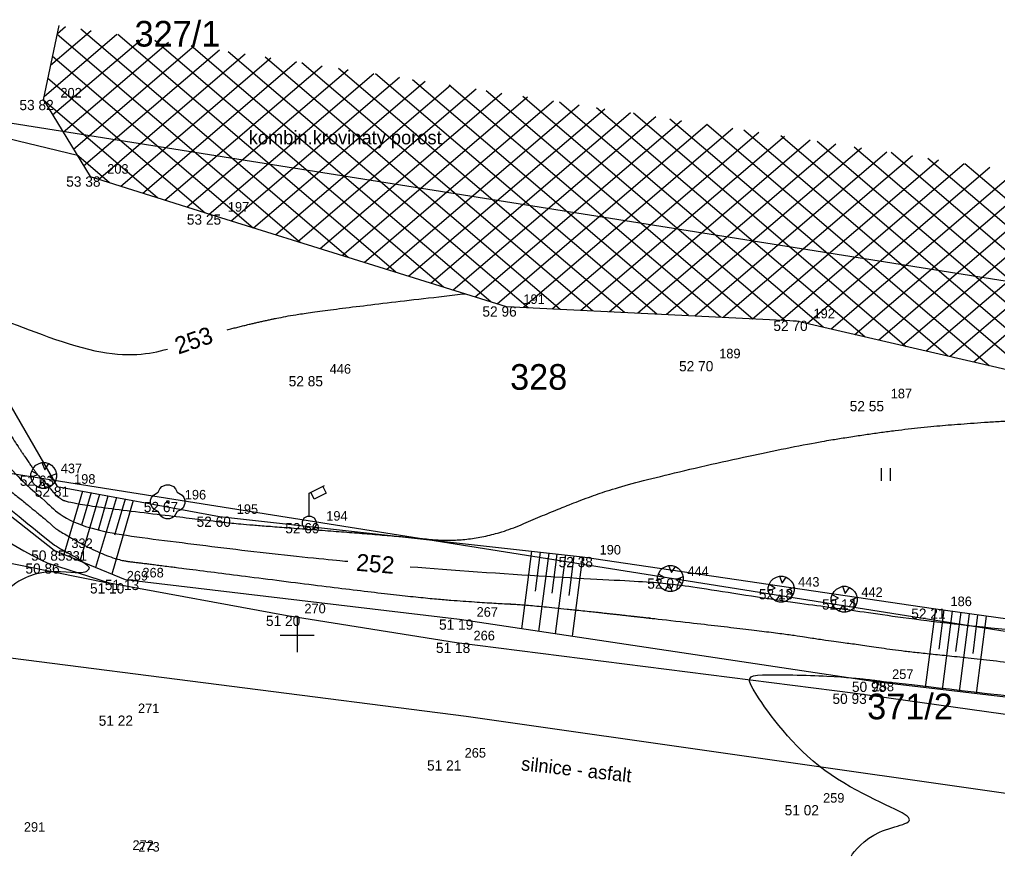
# Model space of a CAD drawing. Extents: x -704057 to -703795, y -1008732 to -1008584.
# Drawn here: x -703983.13 to -703954.51, y -1008656.35 to -1008631.99 of the extents above; entities that cross this region are included whole.
import ezdxf

# ---------------------------------------------------------------- set-up
doc = ezdxf.new("R2010")
doc.units = 0
for name, color, linetype in [('Z_body', 7, 'Continuous'), ('Z_body_cisla', 7, 'Continuous'), ('Z_body_vysky', 7, 'Continuous'), ('Z_hekt_sit', 7, 'Continuous'), ('Z_katastr_cisla_pozemkove', 7, 'Continuous'), ('Z_katastr_hranice', 7, 'Continuous'), ('Z_katastr_hranice_KU', 7, 'Continuous'), ('Z_komunikace_zpevn_pl', 7, 'Continuous'), ('Z_popis', 7, 'Continuous'), ('Z_site_znaky_VO', 7, 'Continuous'), ('Z_teren_hrany_paty', 7, 'Continuous'), ('Z_vrstevnice_popis', 7, 'Continuous'), ('Z_vrstevnice_vedlejsi', 7, 'Continuous'), ('Z_zelen_jednotliva', 7, 'Continuous'), ('Z_zelen_souvisla', 7, 'Continuous')]:
    doc.layers.add(name, color=color, linetype=linetype)

# ---------------------------------------------------------------- blocks, each defined once
blk = doc.blocks.new('POINT_DISPLAY')
blk.add_line((0, 0), (0, 0))
blk = doc.blocks.new('Z24')
for p, q in [((-0.28, 0.28), (-0.23, 0.38)), ((-0.23, 0.38), (-0.17, 0.45)), ((-0.17, 0.45), (-0.05, 0.5)), ((-0.05, 0.5), (0.05, 0.5)), ((0.05, 0.5), (0.17, 0.45)), ((0.17, 0.45), (0.23, 0.38)), ((0.23, 0.38), (0.28, 0.28)), ((-0.5, 0.05), (-0.47, 0.13)), ((-0.5, -0.05), (-0.5, 0.05)), ((-0.47, 0.13), (-0.42, 0.2)), ((-0.42, 0.2), (-0.28, 0.28)), ((-0.03, -0.03), (-0.03, 0.03)), ((-0.03, 0.03), (0.03, 0.03)), ((0.03, 0.03), (0.03, -0.03)), ((0.28, 0.28), (0.42, 0.2)), ((0.42, 0.2), (0.47, 0.13)), ((0.47, 0.13), (0.5, 0.05)), ((0.5, 0.05), (0.5, -0.05)), ((-0.45, -0.17), (-0.5, -0.05)), ((-0.38, -0.23), (-0.45, -0.17)), ((-0.28, -0.28), (-0.38, -0.23)), ((-0.2, -0.42), (-0.28, -0.28)), ((0.03, -0.03), (-0.03, -0.03)), ((0.28, -0.28), (0.2, -0.42)), ((0.38, -0.23), (0.28, -0.28)), ((0.45, -0.17), (0.38, -0.23)), ((0.5, -0.05), (0.45, -0.17)), ((-0.13, -0.47), (-0.2, -0.42)), ((-0.05, -0.5), (-0.13, -0.47)), ((0.05, -0.5), (-0.05, -0.5)), ((0.13, -0.47), (0.05, -0.5)), ((0.2, -0.42), (0.13, -0.47))]:
    blk.add_line(p, q)
blk = doc.blocks.new('Z23')
for p, q in [((-0.3, 0.23), (-0.23, 0.3)), ((-0.23, 0.3), (-0.13, 0.35)), ((-0.13, 0.35), (-0.05, 0.38)), ((-0.05, 0.38), (0.05, 0.38)), ((-0.05, 0.38), (0.03, 0.17)), ((0.03, 0.17), (0.15, 0.35)), ((0.05, 0.38), (0.15, 0.35)), ((0.15, 0.35), (0.23, 0.3)), ((0.23, 0.3), (0.3, 0.23)), ((-0.38, 0.05), (-0.35, 0.13)), ((-0.38, -0.05), (-0.38, 0.05)), ((-0.38, -0.05), (-0.17, 0.03)), ((-0.35, 0.13), (-0.3, 0.23)), ((-0.17, 0.03), (-0.35, 0.13)), ((0.38, 0.05), (0.17, -0.03)), ((0.3, 0.23), (0.35, 0.15)), ((0.35, 0.15), (0.38, 0.05)), ((0.38, 0.05), (0.38, -0.05)), ((-0.35, -0.13), (-0.38, -0.05)), ((-0.3, -0.23), (-0.35, -0.13)), ((-0.23, -0.3), (-0.3, -0.23)), ((-0.15, -0.35), (-0.03, -0.17)), ((-0.03, -0.17), (0.05, -0.38)), ((0.17, -0.03), (0.35, -0.15)), ((0.3, -0.23), (0.23, -0.3)), ((0.35, -0.15), (0.3, -0.23)), ((0.38, -0.05), (0.35, -0.15)), ((-0.15, -0.35), (-0.23, -0.3)), ((-0.05, -0.38), (-0.15, -0.35)), ((0.05, -0.38), (-0.05, -0.38)), ((0.15, -0.35), (0.05, -0.38)), ((0.23, -0.3), (0.15, -0.35))]:
    blk.add_line(p, q)
blk = doc.blocks.new('Z13')
for p, q in [((0, 0.88), (0.45, 1.1)), ((0, 0.2), (0, 0.88)), ((0.15, 0.7), (0.05, 0.9)), ((0.5, 0.88), (0.15, 0.7)), ((0.4, 1.07), (0.5, 0.88)), ((-0.2, 0.05), (-0.15, 0.15)), ((-0.2, -0.05), (-0.2, 0.05)), ((-0.15, 0.15), (-0.05, 0.2)), ((-0.05, 0.2), (0.05, 0.2)), ((0.05, 0.2), (0.15, 0.15)), ((0.15, 0.15), (0.2, 0.05)), ((0.2, 0.05), (0.2, -0.05)), ((-0.15, -0.15), (-0.2, -0.05)), ((-0.05, -0.2), (-0.15, -0.15)), ((0.05, -0.2), (-0.05, -0.2)), ((0.15, -0.15), (0.05, -0.2)), ((0.2, -0.05), (0.15, -0.15))]:
    blk.add_line(p, q)
blk = doc.blocks.new('Z306')
for p, q in [((-0.13, 0.17), (-0.13, -0.2)), ((0.13, 0.17), (0.13, -0.2))]:
    blk.add_line(p, q)

msp = doc.modelspace()

# ---------------------------------------------------------------- linework, layer by layer
at = {"layer": 'Z_hekt_sit'}
for p, q in [((-703975, -1008649.5), (-703975, -1008650.5)), ((-703975.5, -1008650), (-703974.5, -1008650))]:
    msp.add_line(p, q, dxfattribs=at)
at = {"layer": 'Z_katastr_hranice'}
for p, q in [((-703948.06, -1008640.63), (-703989.44, -1008634.06)), ((-703993.4, -1008643.68), (-703944.4, -1008651.45))]:
    msp.add_line(p, q, dxfattribs=at)
at = {"layer": 'Z_katastr_hranice_KU'}
for p, q in [((-703989.65, -1008649.86), (-703970.06, -1008652.37)), ((-703970.06, -1008652.37), (-703947.15, -1008655.63))]:
    msp.add_line(p, q, dxfattribs=at)
at = {"layer": 'Z_komunikace_zpevn_pl'}
for p, q in [((-703988.96, -1008646.77), (-703980.49, -1008648.48)), ((-703980.49, -1008648.48), (-703982.28, -1008647.9)), ((-703975.29, -1008649.43), (-703980.49, -1008648.48)), ((-703970.34, -1008650.22), (-703975.29, -1008649.43)), ((-703958.66, -1008651.71), (-703970.34, -1008650.22)), ((-703949.88, -1008652.93), (-703958.66, -1008651.71))]:
    msp.add_line(p, q, dxfattribs=at)
msp.add_arc((-703977.91, -1008638.41), 10.448, 198.1269, 245.2768, dxfattribs=at)
at = {"layer": 'Z_teren_hrany_paty'}
for p, q in [((-703984.91, -1008640.66), (-703982.03, -1008645.65)), ((-703982.11, -1008647.52), (-703985.68, -1008644.72)), ((-703982.03, -1008645.65), (-703977.27, -1008646.53)), ((-703981.28, -1008645.79), (-703981.83, -1008647.64)), ((-703980.79, -1008645.88), (-703981.36, -1008647.83)), ((-703981.03, -1008645.83), (-703981.31, -1008646.78)), ((-703980.29, -1008645.97), (-703980.9, -1008648.02)), ((-703980.54, -1008645.93), (-703980.83, -1008646.93)), ((-703980.04, -1008646.02), (-703980.35, -1008647.07)), ((-703979.8, -1008646.06), (-703980.43, -1008648.21)), ((-703977.27, -1008646.53), (-703966.65, -1008647.71)), ((-703980.03, -1008648.38), (-703982.11, -1008647.52)), ((-703968.14, -1008647.54), (-703968.44, -1008649.81)), ((-703967.89, -1008647.57), (-703968.04, -1008648.71)), ((-703967.64, -1008647.6), (-703967.94, -1008649.89)), ((-703967.4, -1008647.63), (-703967.55, -1008648.77)), ((-703967.15, -1008647.65), (-703967.45, -1008649.96)), ((-703966.9, -1008647.68), (-703967.05, -1008648.84)), ((-703966.65, -1008647.71), (-703966.95, -1008650.03)), ((-703966.65, -1008647.71), (-703956.38, -1008649.22)), ((-703970.25, -1008649.54), (-703980.03, -1008648.38)), ((-703956.32, -1008649.23), (-703956.62, -1008651.53)), ((-703956.38, -1008649.22), (-703947.47, -1008650.47)), ((-703956.08, -1008649.26), (-703956.22, -1008650.41)), ((-703955.83, -1008649.3), (-703956.12, -1008651.59)), ((-703955.58, -1008649.33), (-703955.73, -1008650.48)), ((-703955.33, -1008649.37), (-703955.63, -1008651.65)), ((-703955.09, -1008649.4), (-703955.23, -1008650.54)), ((-703954.84, -1008649.44), (-703955.13, -1008651.71)), ((-703958.09, -1008651.36), (-703970.25, -1008649.54)), ((-703949.1, -1008652.42), (-703958.09, -1008651.36))]:
    msp.add_line(p, q, dxfattribs=at)
at = {"layer": 'Z_vrstevnice_popis'}
for points, degree in [([(-703989.544, -1008635.313), (-703988.902, -1008636.056), (-703987.798, -1008637.865), (-703987.151, -1008639.438), (-703986.053, -1008641.144), (-703985.706, -1008641.697), (-703984.977, -1008642.908), (-703983.536, -1008645.121), (-703982.31, -1008646.105), (-703982.063, -1008646.423), (-703981.066, -1008646.966), (-703978.397, -1008647.285), (-703975.56, -1008647.648), (-703973.643, -1008647.827), (-703973.517, -1008647.838)], 3), ([(-703987.108, -1008635.508), (-703986.754, -1008636.087), (-703984.996, -1008640.365), (-703984.718, -1008640.456), (-703984.363, -1008640.44), (-703980.63, -1008641.987), (-703979.311, -1008641.778), (-703978.799, -1008641.628)], 3), ([(-703977.053, -1008641.068), (-703976.067, -1008640.807), (-703974.358, -1008640.497), (-703970.073, -1008640.009)], 2), ([(-703989.503, -1008643.449), (-703989.267, -1008643.557), (-703988.594, -1008643.878), (-703987.719, -1008644.81), (-703986.755, -1008645.399), (-703986.308, -1008645.619), (-703984.807, -1008646.186), (-703985.704, -1008645.225), (-703986.427, -1008644.081), (-703986.268, -1008643.227), (-703985.558, -1008644.406), (-703985.308, -1008644.79), (-703982.136, -1008647.335), (-703982.104, -1008647.377), (-703980.996, -1008647.981), (-703981.138, -1008648.096), (-703981.236, -1008648.238), (-703982.91, -1008647.991), (-703984.29, -1008649.466), (-703985.601, -1008651.032), (-703985.434, -1008652.571), (-703985.359, -1008653.111)], 3), ([(-703971.691, -1008647.995), (-703970.514, -1008648.089), (-703967.379, -1008648.313), (-703964.571, -1008648.435), (-703963.695, -1008648.534), (-703960.428, -1008649.057), (-703958.881, -1008649.241), (-703956.672, -1008649.585), (-703952.719, -1008649.987), (-703950.97, -1008650.177), (-703947.545, -1008650.56), (-703946.3, -1008650.665), (-703945.127, -1008650.72), (-703944.757, -1008650.678), (-703944.314, -1008650.608), (-703943.915, -1008650.57), (-703942.581, -1008649.228), (-703940.433, -1008648.504), (-703938.207, -1008647.326), (-703935.929, -1008646.808), (-703934.536, -1008646.556), (-703934.13, -1008646.489)], 3), ([(-703958.782, -1008656.452), (-703958.711, -1008656.345), (-703958.126, -1008655.591), (-703956.246, -1008655.482), (-703959.788, -1008654.246), (-703961.93, -1008651.293), (-703961.78, -1008651.126), (-703959.248, -1008651.187), (-703958.2, -1008651.305), (-703958.136, -1008651.315), (-703958.106, -1008651.318), (-703958.062, -1008651.325), (-703957.976, -1008651.334), (-703949.197, -1008652.35), (-703949.055, -1008652.366), (-703948.978, -1008652.372), (-703948.89, -1008652.368), (-703940.582, -1008653.06), (-703940.108, -1008653.095), (-703933.647, -1008653.758), (-703931.403, -1008653.997), (-703930.745, -1008653.985), (-703930.26, -1008654), (-703929.245, -1008652.825), (-703928.701, -1008652.453), (-703928.643, -1008652.6), (-703928.429, -1008652.279), (-703926.218, -1008652.574), (-703924.884, -1008652.504), (-703924.716, -1008652.484), (-703922.063, -1008653.995), (-703921.911, -1008654.006), (-703921.781, -1008654.024), (-703921.558, -1008654.048), (-703920.173, -1008654.162), (-703919.91, -1008654.188), (-703916.508, -1008654.023), (-703914.694, -1008654.331), (-703914.465, -1008654.432), (-703913.706, -1008654.968), (-703913.145, -1008655.151), (-703910.497, -1008655.228), (-703905.972, -1008655.203), (-703903.752, -1008655.504), (-703902.532, -1008655.695)], 3), ([(-703985.231, -1008654.773), (-703985.233, -1008654.99), (-703985.209, -1008655.538), (-703984.22, -1008656.692), (-703983.2, -1008656.858), (-703982.505, -1008657.462), (-703981.889, -1008657.948), (-703981.945, -1008658.047), (-703982.027, -1008658.206), (-703982.128, -1008658.577), (-703982.119, -1008658.578), (-703981.97, -1008658.325), (-703981.459, -1008658.081), (-703981.513, -1008658.577), (-703981.415, -1008659.217), (-703981.332, -1008659.732), (-703980.559, -1008660.215), (-703980.405, -1008660.435), (-703979.463, -1008659.63), (-703979.059, -1008659.888), (-703977.693, -1008660.229), (-703973.778, -1008660.657)], 3)]:
    msp.add_open_spline(points, degree=degree, dxfattribs=at)
at = {"layer": 'Z_vrstevnice_vedlejsi'}
msp.add_line((-703981.434, -1008635.969), (-703985.029, -1008635.098), dxfattribs=at)
for points in [[(-704009.362, -1008633.586), (-704007.915, -1008634.739), (-704007.143, -1008635.358), (-704002.876, -1008638.286), (-704002.679, -1008638.43), (-704002.255, -1008638.718), (-704001.165, -1008638.717), (-703995.889, -1008642.289), (-703994.89, -1008642.862), (-703994.417, -1008642.752), (-703993.832, -1008642.719), (-703993.258, -1008640.696), (-703993.341, -1008639.701), (-703993.272, -1008639.432), (-703993.04, -1008638.835), (-703992.99, -1008638.745), (-703990.403, -1008638.423), (-703989.481, -1008638.539), (-703989.058, -1008638.588), (-703989.018, -1008638.516), (-703988.578, -1008638.54), (-703988.475, -1008638.554), (-703988.362, -1008638.685), (-703988.319, -1008638.754), (-703988.294, -1008638.815), (-703986.637, -1008641.391), (-703986.518, -1008641.581), (-703985.267, -1008643.657), (-703984.422, -1008644.955), (-703982.223, -1008646.72), (-703982.083, -1008646.9), (-703980.47, -1008647.779), (-703979.335, -1008647.914), (-703971.793, -1008648.878), (-703969.312, -1008649.063), (-703968.076, -1008649.117), (-703960.948, -1008649.919), (-703959.282, -1008650.186), (-703958.493, -1008650.28), (-703957.367, -1008650.455), (-703955.116, -1008650.684), (-703950.816, -1008651.182), (-703948.3, -1008651.463), (-703946.953, -1008651.576), (-703945.397, -1008651.505), (-703943.023, -1008651.703), (-703939.161, -1008651.987), (-703938.27, -1008652.079), (-703937.191, -1008652.194), (-703934.147, -1008651.524), (-703931.028, -1008650.815), (-703930.717, -1008650.764), (-703928.94, -1008650.83), (-703928.501, -1008650.751), (-703928.424, -1008650.713), (-703928.413, -1008650.708), (-703928.266, -1008650.724), (-703926.027, -1008648.737), (-703920.5, -1008648.624), (-703915.824, -1008649.925), (-703908.88, -1008649.843), (-703904.651, -1008650.155), (-703897.103, -1008651.333), (-703893.743, -1008651.997), (-703889.99, -1008652.252), (-703881.693, -1008653.228), (-703874.656, -1008652.961), (-703868.448, -1008652.365), (-703859.857, -1008652.906), (-703856.36, -1008653.001), (-703843.765, -1008653.766), (-703842.17, -1008653.801), (-703841.143, -1008653.824), (-703831.904, -1008654.28)], [(-703988.164, -1008635.52), (-703987.276, -1008636.976), (-703986.008, -1008640.062), (-703985.47, -1008640.897), (-703984.895, -1008641.813), (-703984.686, -1008642.159), (-703982.65, -1008645.287), (-703982.397, -1008645.49), (-703982.043, -1008645.946), (-703981.661, -1008646.154), (-703977.458, -1008646.656), (-703976.772, -1008646.743), (-703972.443, -1008647.066), (-703969.747, -1008647.327), (-703967.111, -1008646.193), (-703965.337, -1008645.561), (-703960.636, -1008644.491), (-703957.873, -1008644.043), (-703955.63, -1008643.808), (-703952.03, -1008643.609), (-703943.212, -1008644.531), (-703942.275, -1008644.62), (-703942.236, -1008644.645), (-703942.208, -1008644.623), (-703942.168, -1008644.583), (-703942.126, -1008644.569), (-703941.982, -1008644.492), (-703939.179, -1008642.975), (-703937.245, -1008642.629)]]:
    msp.add_open_spline(points, degree=2, dxfattribs=at)
at = {"layer": 'Z_zelen_souvisla'}
for p, q in [((-703982.43, -1008634.34), (-703981.97, -1008632.16)), ((-703982.22, -1008633.32), (-703981.03, -1008632.31)), ((-703982.02, -1008632.4), (-703981.78, -1008632.19)), ((-703981.33, -1008632.26), (-703973.51, -1008638.94)), ((-703982.41, -1008634.24), (-703980.28, -1008632.42)), ((-703982.16, -1008634.78), (-703979.53, -1008632.54)), ((-703982.03, -1008632.42), (-703974.9, -1008638.51)), ((-703980.25, -1008632.42), (-703972.11, -1008639.37)), ((-703979.17, -1008632.59), (-703970.72, -1008639.81)), ((-703981.85, -1008635.28), (-703978.77, -1008632.65)), ((-703981.55, -1008635.78), (-703978.02, -1008632.76)), ((-703981.25, -1008636.27), (-703977.27, -1008632.88)), ((-703978.1, -1008632.75), (-703969.33, -1008640.24)), ((-703982.16, -1008633.06), (-703976.29, -1008638.08)), ((-703980.81, -1008636.66), (-703976.52, -1008632.99)), ((-703980.16, -1008636.86), (-703975.77, -1008633.11)), ((-703977.02, -1008632.92), (-703968.24, -1008640.41)), ((-703975.94, -1008633.08), (-703967.3, -1008640.46)), ((-703979.52, -1008637.07), (-703975.02, -1008633.22)), ((-703978.87, -1008637.27), (-703974.27, -1008633.34)), ((-703978.22, -1008637.47), (-703973.51, -1008633.45)), ((-703974.86, -1008633.25), (-703966.36, -1008640.5)), ((-703973.79, -1008633.41), (-703965.42, -1008640.55)), ((-703982.3, -1008633.7), (-703977.69, -1008637.64)), ((-703977.58, -1008637.68), (-703972.76, -1008633.57)), ((-703976.93, -1008637.88), (-703972.01, -1008633.68)), ((-703972.71, -1008633.57), (-703964.48, -1008640.6)), ((-703971.63, -1008633.74), (-703963.55, -1008640.64)), ((-703976.28, -1008638.08), (-703971.26, -1008633.79)), ((-703975.63, -1008638.28), (-703970.51, -1008633.91)), ((-703974.98, -1008638.48), (-703969.76, -1008634.02)), ((-703970.55, -1008633.9), (-703962.61, -1008640.69)), ((-703974.33, -1008638.69), (-703969.01, -1008634.14)), ((-703973.68, -1008638.89), (-703968.26, -1008634.25)), ((-703969.47, -1008634.07), (-703961.67, -1008640.74)), ((-703968.4, -1008634.23), (-703960.73, -1008640.78)), ((-703982.43, -1008634.34), (-703981.06, -1008636.58)), ((-703982.42, -1008634.35), (-703979.09, -1008637.2)), ((-703973.03, -1008639.09), (-703967.5, -1008634.37)), ((-703972.38, -1008639.29), (-703966.75, -1008634.48)), ((-703971.73, -1008639.49), (-703966, -1008634.6)), ((-703967.32, -1008634.4), (-703959.61, -1008640.98)), ((-703966.24, -1008634.56), (-703958.39, -1008641.26)), ((-703971.08, -1008639.69), (-703965.25, -1008634.71)), ((-703970.44, -1008639.9), (-703964.5, -1008634.83)), ((-703965.16, -1008634.72), (-703957.18, -1008641.55)), ((-703969.79, -1008640.1), (-703963.75, -1008634.94)), ((-703969.14, -1008640.3), (-703963, -1008635.05)), ((-703968.38, -1008640.4), (-703962.25, -1008635.17)), ((-703964.09, -1008634.89), (-703955.96, -1008641.83)), ((-703963.01, -1008635.05), (-703954.75, -1008642.11)), ((-703967.54, -1008640.45), (-703961.49, -1008635.28)), ((-703966.7, -1008640.49), (-703960.74, -1008635.4)), ((-703961.93, -1008635.22), (-703953.53, -1008642.39)), ((-703960.85, -1008635.38), (-703952.32, -1008642.67)), ((-703965.86, -1008640.53), (-703959.99, -1008635.51)), ((-703965.03, -1008640.57), (-703959.24, -1008635.63)), ((-703964.19, -1008640.61), (-703958.49, -1008635.74)), ((-703959.78, -1008635.55), (-703951.2, -1008642.87)), ((-703958.7, -1008635.71), (-703950.08, -1008643.07)), ((-703981.46, -1008635.93), (-703980.49, -1008636.76)), ((-703963.35, -1008640.65), (-703957.74, -1008635.86)), ((-703962.52, -1008640.69), (-703956.99, -1008635.97)), ((-703957.62, -1008635.87), (-703948.96, -1008643.27)), ((-703961.68, -1008640.74), (-703956.23, -1008636.09)), ((-703960.84, -1008640.78), (-703955.48, -1008636.2)), ((-703960.07, -1008640.87), (-703954.73, -1008636.31)), ((-703956.54, -1008636.04), (-703947.84, -1008643.47)), ((-703955.46, -1008636.2), (-703946.72, -1008643.67)), ((-703981.06, -1008636.58), (-703977.53, -1008637.69)), ((-703959.37, -1008641.04), (-703953.98, -1008636.43)), ((-703958.68, -1008641.2), (-703953.23, -1008636.54)), ((-703957.98, -1008641.36), (-703952.48, -1008636.66)), ((-703957.29, -1008641.52), (-703951.73, -1008636.77)), ((-703956.59, -1008641.68), (-703950.98, -1008636.89)), ((-703955.89, -1008641.84), (-703950.22, -1008637)), ((-703955.2, -1008642), (-703949.47, -1008637.12)), ((-703977.53, -1008637.69), (-703968.88, -1008640.38)), ((-703968.88, -1008640.38), (-703960.39, -1008640.8)), ((-703960.39, -1008640.8), (-703952.33, -1008642.67))]:
    msp.add_line(p, q, dxfattribs=at)

# ---------------------------------------------------------------- block references
at = {"layer": 'Z_body'}
for p in [(-703982.43, -1008634.34), (-703981.06, -1008636.58), (-703977.53, -1008637.69), (-703968.88, -1008640.38), (-703960.39, -1008640.8), (-703963.15, -1008641.98), (-703974.55, -1008642.42), (-703958.13, -1008643.15), (-703982.42, -1008645.33), (-703982.03, -1008645.65), (-703978.79, -1008646.1), (-703977.27, -1008646.53), (-703974.65, -1008646.72), (-703982.11, -1008647.52), (-703966.65, -1008647.71), (-703982.28, -1008647.9), (-703980.49, -1008648.48), (-703980.03, -1008648.38), (-703964.08, -1008648.34), (-703960.84, -1008648.65), (-703958.99, -1008648.95), (-703975.29, -1008649.43), (-703956.38, -1008649.22), (-703970.25, -1008649.54), (-703970.34, -1008650.22), (-703958.09, -1008651.36), (-703958.66, -1008651.71), (-703980.16, -1008652.35), (-703970.6, -1008653.66), (-703960.11, -1008654.97)]:
    msp.add_blockref('POINT_DISPLAY', p, dxfattribs=at)
at = {"layer": 'Z_popis'}
msp.add_blockref('Z306', (-703957.78, -1008645.28), dxfattribs=at)
at = {"layer": 'Z_site_znaky_VO'}
msp.add_blockref('Z13', (-703974.65, -1008646.72), dxfattribs=at)
at = {"layer": 'Z_zelen_jednotliva'}
for name, p in [('Z23', (-703982.42, -1008645.33)), ('Z24', (-703978.79, -1008646.1)), ('Z23', (-703964.08, -1008648.34)), ('Z23', (-703960.84, -1008648.65)), ('Z23', (-703958.99, -1008648.95))]:
    msp.add_blockref(name, p, dxfattribs=at)

# ---------------------------------------------------------------- texts
at = {"layer": 'Z_body_cisla'}
for s, p in [('202', (-703981.93, -1008634.27)), ('203', (-703980.56, -1008636.5)), ('197', (-703977.03, -1008637.61)), ('191', (-703968.38, -1008640.31)), ('192', (-703959.89, -1008640.73)), ('189', (-703962.65, -1008641.9)), ('446', (-703974.05, -1008642.35)), ('187', (-703957.63, -1008643.07)), ('437', (-703981.92, -1008645.26)), ('198', (-703981.53, -1008645.57)), ('196', (-703978.29, -1008646.03)), ('195', (-703976.77, -1008646.45)), ('194', (-703974.15, -1008646.65)), ('332', (-703981.61, -1008647.45)), ('190', (-703966.15, -1008647.64)), ('331', (-703981.78, -1008647.82)), ('268', (-703979.53, -1008648.31)), ('444', (-703963.58, -1008648.27)), ('269', (-703979.99, -1008648.4)), ('443', (-703960.34, -1008648.58)), ('442', (-703958.49, -1008648.88)), ('186', (-703955.88, -1008649.15)), ('270', (-703974.79, -1008649.36)), ('267', (-703969.75, -1008649.46)), ('266', (-703969.84, -1008650.15)), ('257', (-703957.59, -1008651.28)), ('258', (-703958.16, -1008651.64)), ('271', (-703979.66, -1008652.28)), ('265', (-703970.1, -1008653.58)), ('259', (-703959.61, -1008654.9)), ('291', (-703983, -1008655.75)), ('272', (-703979.82, -1008656.28)), ('273', (-703979.65, -1008656.33))]:
    msp.add_text(s, height=0.28, dxfattribs=at).set_placement(p)
at = {"layer": 'Z_body_vysky'}
for s, p in [('53 82', (-703983.13, -1008634.64)), ('53 38', (-703981.76, -1008636.88)), ('53 25', (-703978.23, -1008637.99)), ('52 96', (-703969.58, -1008640.68)), ('52 70', (-703961.065, -1008641.1)), ('52 70', (-703963.825, -1008642.28)), ('52 85', (-703975.25, -1008642.72)), ('52 55', (-703958.83, -1008643.45)), ('52 63', (-703983.12, -1008645.63)), ('52 81', (-703982.68, -1008645.95)), ('52 67', (-703979.49, -1008646.4)), ('52 60', (-703977.945, -1008646.83)), ('52 69', (-703975.35, -1008647.02)), ('50 85', (-703982.785, -1008647.82)), ('52 38', (-703967.35, -1008648.01)), ('50 86', (-703982.955, -1008648.2)), ('52 07', (-703964.755, -1008648.64)), ('51 10', (-703981.065, -1008648.78)), ('51 13', (-703980.63, -1008648.68)), ('52 18', (-703961.49, -1008648.95)), ('52 14', (-703959.64, -1008649.25)), ('51 20', (-703975.915, -1008649.73)), ('52 21', (-703957.03, -1008649.52)), ('51 19', (-703970.85, -1008649.84)), ('51 18', (-703970.94, -1008650.52)), ('50 98', (-703958.765, -1008651.66)), ('50 93', (-703959.335, -1008652.01)), ('51 22', (-703980.81, -1008652.65)), ('51 21', (-703971.2, -1008653.96)), ('51 02', (-703960.735, -1008655.27))]:
    msp.add_text(s, height=0.3, dxfattribs=at).set_placement(p)
at = {"layer": 'Z_katastr_cisla_pozemkove'}
for s, p in [('327/1', (-703979.76, -1008632.78)), ('328', (-703968.77, -1008642.82)), ('371/2', (-703958.32, -1008652.46))]:
    msp.add_text(s, height=0.75, dxfattribs=at).set_placement(p)
at = {"layer": 'Z_popis'}
msp.add_text('kombin.krovinaty porost', height=0.4, dxfattribs=at).set_placement((-703976.42, -1008635.64))
msp.add_text('silnice - asfalt', height=0.4, rotation=353.7, dxfattribs=at).set_placement((-703968.46, -1008653.95))
at = {"layer": 'Z_vrstevnice_popis'}
for s, rotation, p in [('253', 18.9665, (-703978.478, -1008641.792)), ('252', 355.1171, (-703973.29, -1008648.112))]:
    msp.add_text(s, height=0.5, rotation=rotation, dxfattribs=at).set_placement(p)

doc.saveas('drawing.dxf')
